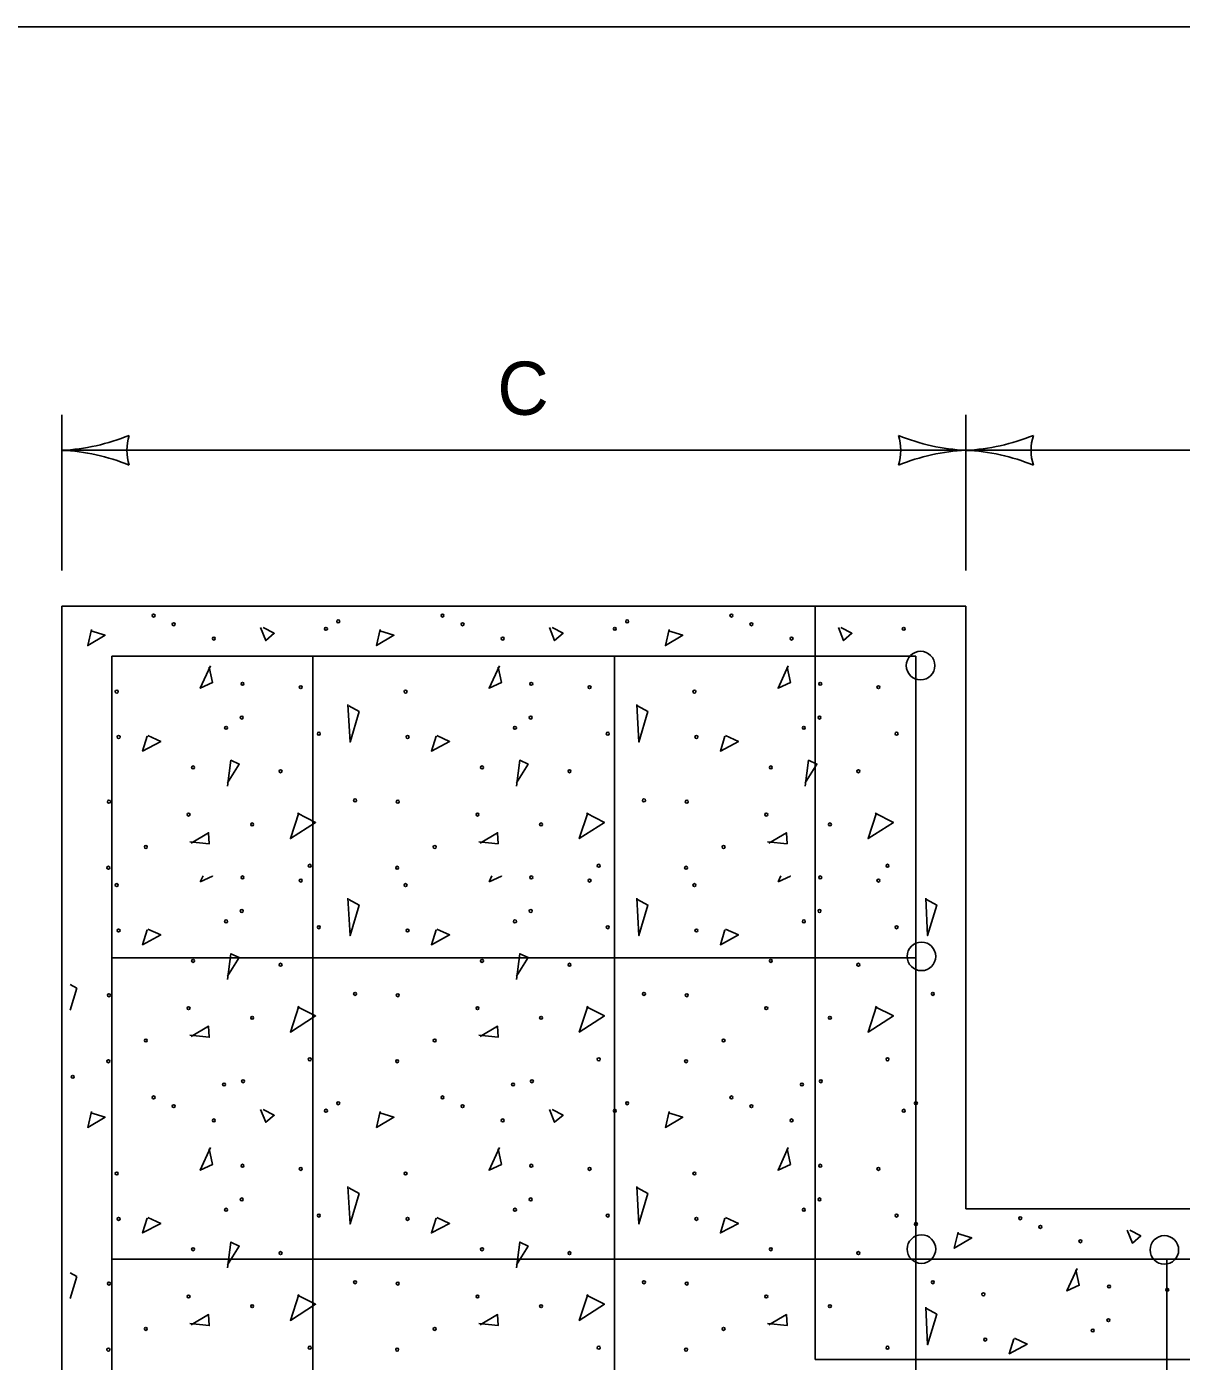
# Model space of a CAD drawing. Extents: x 49991.4 to 50021, y 49987.6 to 50011.4.
# Drawn here: x 50012.304 to 50013.607, y 49997.494 to 49998.999 of the extents above; entities that cross this region are included whole.
import ezdxf

# ---------------------------------------------------------------- set-up
doc = ezdxf.new("R2010")
doc.units = 0
for name, color, linetype in [('Level 1', 7, 'Continuous'), ('Level 2', 7, 'Continuous'), ('Level 3', 7, 'Continuous'), ('Level 4', 7, 'Continuous')]:
    doc.layers.add(name, color=color, linetype=linetype)

msp = doc.modelspace()

# ---------------------------------------------------------------- linework, layer by layer
at = {"layer": 'Level 1'}
for p, q in [((50012.3438, 49997.1556), (50012.3438, 49998.3456)), ((50012.3438, 49998.3456), (50013.3637, 49998.3456)), ((50013.3637, 49998.3456), (50013.3637, 49997.6657)), ((50012.4004, 49998.289), (50013.3071, 49998.289)), ((50012.4004, 49998.289), (50012.4004, 49997.2122)), ((50012.6271, 49998.289), (50012.6271, 49997.2122)), ((50012.9671, 49998.289), (50012.9671, 49997.2122)), ((50013.3071, 49998.289), (50013.3071, 49997.2122)), ((50012.4004, 49997.949), (50013.3071, 49997.949)), ((50013.3637, 49997.6657), (50014.0437, 49997.6657)), ((50012.4004, 49997.609), (50015.007, 49997.609)), ((50013.5904, 49997.609), (50013.5904, 49997.2122))]:
    msp.add_line(p, q, dxfattribs=at)
msp.add_lwpolyline([(49999.3835, 49998.9992), (50016.7501, 49998.9992), (50016.7501, 49987.7988), (49999.3835, 49987.7988)], close=True, dxfattribs=at)
for points in [[(50012.3773, 49998.3193), (50012.373, 49998.301), (50012.3926, 49998.3127), (50012.3766, 49998.3178)], [(50012.568, 49998.3214), (50012.5739, 49998.3068), (50012.5834, 49998.3149), (50012.571, 49998.3214)], [(50012.7031, 49998.3193), (50012.6988, 49998.301), (50012.7185, 49998.3127), (50012.7024, 49998.3178)], [(50012.894, 49998.3214), (50012.8997, 49998.3068), (50012.9093, 49998.3149), (50012.8968, 49998.3214)], [(50013.029, 49998.3193), (50013.0246, 49998.301), (50013.0443, 49998.3127), (50013.0282, 49998.3178)], [(50013.2198, 49998.3214), (50013.2256, 49998.3068), (50013.2351, 49998.3149), (50013.2227, 49998.3214)], [(50012.5117, 49998.2784), (50012.5, 49998.2529), (50012.5138, 49998.2594), (50012.5102, 49998.2769)], [(50012.8375, 49998.2784), (50012.8258, 49998.2529), (50012.8397, 49998.2594), (50012.836, 49998.2769)], [(50013.1633, 49998.2784), (50013.1517, 49998.2529), (50013.1656, 49998.2594), (50013.1619, 49998.2769)], [(50012.6666, 49998.2345), (50012.6689, 49998.1922), (50012.6791, 49998.2266), (50012.6674, 49998.2331)], [(50012.9924, 49998.2345), (50012.9947, 49998.1922), (50013.0049, 49998.2266), (50012.9932, 49998.2331)], [(50012.4401, 49998.1988), (50012.435, 49998.182), (50012.4555, 49998.1929), (50012.4409, 49998.1995)], [(50012.766, 49998.1988), (50012.7608, 49998.182), (50012.7813, 49998.1929), (50012.7667, 49998.1995)], [(50013.0918, 49998.1988), (50013.0867, 49998.182), (50013.1071, 49998.1929), (50013.0925, 49998.1995)], [(50012.5308, 49998.1426), (50012.5345, 49998.1717), (50012.544, 49998.1674), (50012.5308, 49998.1462)], [(50012.8567, 49998.1426), (50012.8603, 49998.1717), (50012.8698, 49998.1674), (50012.8567, 49998.1462)], [(50013.1825, 49998.1426), (50013.1861, 49998.1717), (50013.1956, 49998.1674), (50013.1825, 49998.1462)], [(50012.6112, 49998.1126), (50012.6017, 49998.0834), (50012.6301, 49998.1017), (50012.6097, 49998.1119)], [(50012.937, 49998.1126), (50012.9275, 49998.0834), (50012.9559, 49998.1017), (50012.9355, 49998.1119)], [(50013.2628, 49998.1126), (50013.2533, 49998.0834), (50013.2819, 49998.1017), (50013.2614, 49998.1119)], [(50012.4897, 49998.0783), (50012.5094, 49998.09), (50012.5102, 49998.0775), (50012.4883, 49998.0797)], [(50012.8156, 49998.0783), (50012.8354, 49998.09), (50012.836, 49998.0775), (50012.8142, 49998.0797)], [(50013.1415, 49998.0783), (50013.1612, 49998.09), (50013.1619, 49998.0775), (50013.14, 49998.0797)], [(50012.5031, 49998.0413), (50012.5, 49998.0346)], [(50012.5, 49998.0346), (50012.5138, 49998.0411)], [(50012.5138, 49998.0411), (50012.5138, 49998.0413)], [(50012.8289, 49998.0413), (50012.8258, 49998.0346)], [(50012.8258, 49998.0346), (50012.8397, 49998.0411)], [(50012.8397, 49998.0411), (50012.8397, 49998.0413)], [(50013.1547, 49998.0413), (50013.1517, 49998.0346)], [(50013.1517, 49998.0346), (50013.1656, 49998.0411)], [(50013.1656, 49998.0411), (50013.1655, 49998.0413)], [(50012.6666, 49998.0163), (50012.6689, 49997.9739), (50012.6791, 49998.0083), (50012.6674, 49998.0148)], [(50012.9924, 49998.0163), (50012.9947, 49997.9739), (50013.0049, 49998.0083), (50012.9932, 49998.0148)], [(50013.3184, 49998.0163), (50013.3205, 49997.9739), (50013.3307, 49998.0083), (50013.3191, 49998.0148)], [(50012.4401, 49997.9805), (50012.435, 49997.9637), (50012.4555, 49997.9747), (50012.4409, 49997.9813)], [(50012.766, 49997.9805), (50012.7608, 49997.9637), (50012.7813, 49997.9747), (50012.7667, 49997.9813)], [(50013.0918, 49997.9805), (50013.0867, 49997.9637), (50013.1071, 49997.9747), (50013.0925, 49997.9813)], [(50012.5308, 49997.9243), (50012.5345, 49997.9535), (50012.544, 49997.9491), (50012.5308, 49997.928)], [(50012.8567, 49997.9243), (50012.8603, 49997.9535), (50012.8698, 49997.9491), (50012.8567, 49997.928)], [(50012.3606, 49997.9147), (50012.3531, 49997.9189)], [(50012.3531, 49997.8897), (50012.3606, 49997.9147)], [(50012.6112, 49997.8944), (50012.6017, 49997.8651), (50012.6301, 49997.8834), (50012.6097, 49997.8937)], [(50012.937, 49997.8944), (50012.9275, 49997.8651), (50012.9559, 49997.8834), (50012.9355, 49997.8937)], [(50013.2628, 49997.8944), (50013.2533, 49997.8651), (50013.2819, 49997.8834), (50013.2614, 49997.8937)], [(50012.4897, 49997.86), (50012.5094, 49997.8717), (50012.5102, 49997.8593), (50012.4883, 49997.8615)], [(50012.8156, 49997.86), (50012.8354, 49997.8717), (50012.836, 49997.8593), (50012.8142, 49997.8615)], [(50012.568, 49997.7779), (50012.5739, 49997.7634), (50012.5834, 49997.7713), (50012.571, 49997.7779)], [(50012.894, 49997.7779), (50012.8997, 49997.7634), (50012.9093, 49997.7713), (50012.8968, 49997.7779)], [(50012.3773, 49997.7757), (50012.373, 49997.7575), (50012.3926, 49997.7691), (50012.3766, 49997.7742)], [(50012.7031, 49997.7757), (50012.6988, 49997.7575), (50012.7185, 49997.7691), (50012.7024, 49997.7742)], [(50013.029, 49997.7757), (50013.0246, 49997.7575), (50013.0443, 49997.7691), (50013.0282, 49997.7742)], [(50012.5117, 49997.7348), (50012.5, 49997.7093), (50012.5138, 49997.7159), (50012.5102, 49997.7333)], [(50012.8375, 49997.7348), (50012.8258, 49997.7093), (50012.8397, 49997.7159), (50012.836, 49997.7333)], [(50013.1633, 49997.7348), (50013.1517, 49997.7093), (50013.1656, 49997.7159), (50013.1619, 49997.7333)], [(50012.6666, 49997.691), (50012.6689, 49997.6487), (50012.6791, 49997.683), (50012.6674, 49997.6896)], [(50012.9924, 49997.691), (50012.9947, 49997.6487), (50013.0049, 49997.683), (50012.9932, 49997.6896)], [(50012.4401, 49997.6552), (50012.435, 49997.6385), (50012.4555, 49997.6493), (50012.4409, 49997.6559)], [(50012.766, 49997.6552), (50012.7608, 49997.6385), (50012.7813, 49997.6493), (50012.7667, 49997.6559)], [(50013.0918, 49997.6552), (50013.0867, 49997.6385), (50013.1071, 49997.6493), (50013.0925, 49997.6559)], [(50012.5308, 49997.599), (50012.5345, 49997.6283), (50012.544, 49997.6238), (50012.5308, 49997.6026)], [(50012.8567, 49997.599), (50012.8603, 49997.6283), (50012.8698, 49997.6238), (50012.8567, 49997.6026)], [(50013.3549, 49997.6395), (50013.3504, 49997.6212), (50013.3702, 49997.6329), (50013.3541, 49997.638)], [(50013.5456, 49997.6416), (50013.5515, 49997.627), (50013.5609, 49997.6351), (50013.5485, 49997.6416)], [(50013.4893, 49997.5986), (50013.4775, 49997.5731), (50013.4914, 49997.5796), (50013.4878, 49997.5971)], [(50012.3606, 49997.5893), (50012.3531, 49997.5935)], [(50012.3531, 49997.5644), (50012.3606, 49997.5893)], [(50012.6112, 49997.5691), (50012.6017, 49997.5399), (50012.6301, 49997.5581), (50012.6097, 49997.5683)], [(50012.937, 49997.5691), (50012.9275, 49997.5399), (50012.9559, 49997.5581), (50012.9355, 49997.5683)], [(50013.3184, 49997.5547), (50013.3205, 49997.5124), (50013.3307, 49997.5468), (50013.3191, 49997.5533)], [(50012.4897, 49997.5348), (50012.5094, 49997.5464), (50012.5102, 49997.534), (50012.4883, 49997.5362)], [(50012.8156, 49997.5348), (50012.8354, 49997.5464), (50012.836, 49997.534), (50012.8142, 49997.5362)], [(50013.1415, 49997.5348), (50013.1612, 49997.5464), (50013.1619, 49997.534), (50013.14, 49997.5362)], [(50013.4176, 49997.519), (50013.4125, 49997.5022), (50013.4329, 49997.5131), (50013.4184, 49997.5197)]]:
    msp.add_lwpolyline(points, dxfattribs=at)
for centre, radius in [((50012.4474, 49998.3349), 0.00165), ((50012.7732, 49998.3349), 0.00165), ((50013.0991, 49998.3349), 0.00165), ((50012.47, 49998.3251), 0.00165), ((50012.6418, 49998.32), 0.00165), ((50012.6556, 49998.3284), 0.00165), ((50012.7959, 49998.3251), 0.00165), ((50012.9676, 49998.32), 0.00165), ((50012.9815, 49998.3284), 0.00165), ((50013.1217, 49998.3251), 0.00165), ((50013.2935, 49998.32), 0.00165), ((50012.5153, 49998.309), 0.00165), ((50012.8411, 49998.309), 0.00165), ((50013.167, 49998.309), 0.00165), ((50013.3125, 49998.2785), 0.0161), ((50012.5476, 49998.2579), 0.00165), ((50012.8734, 49998.2579), 0.00165), ((50013.1993, 49998.2579), 0.00165), ((50012.4057, 49998.2491), 0.00165), ((50012.6133, 49998.2542), 0.00165), ((50012.7316, 49998.2491), 0.00165), ((50012.9391, 49998.2542), 0.00165), ((50013.0574, 49998.2491), 0.00165), ((50013.265, 49998.2542), 0.00165), ((50012.5468, 49998.2199), 0.00165), ((50012.8727, 49998.2199), 0.00165), ((50013.1985, 49998.2199), 0.00165), ((50012.4079, 49998.198), 0.00165), ((50012.5291, 49998.2083), 0.00165), ((50012.6337, 49998.2017), 0.00165), ((50012.7338, 49998.198), 0.00165), ((50012.855, 49998.2083), 0.00165), ((50012.9596, 49998.2017), 0.00165), ((50013.0596, 49998.198), 0.00165), ((50013.1808, 49998.2083), 0.00165), ((50013.2854, 49998.2017), 0.00165), ((50012.4919, 49998.1637), 0.00165), ((50012.5906, 49998.1593), 0.00165), ((50012.8178, 49998.1637), 0.00165), ((50012.9165, 49998.1593), 0.00165), ((50013.1436, 49998.1637), 0.00165), ((50013.2423, 49998.1593), 0.00165), ((50012.397, 49998.125), 0.00165), ((50012.6746, 49998.1265), 0.00165), ((50012.7228, 49998.125), 0.00165), ((50013.0005, 49998.1265), 0.00165), ((50013.0487, 49998.125), 0.00165), ((50012.4868, 49998.1104), 0.00165), ((50012.8127, 49998.1104), 0.00165), ((50013.1385, 49998.1104), 0.00165), ((50012.5585, 49998.0994), 0.00165), ((50012.8844, 49998.0994), 0.00165), ((50013.2102, 49998.0994), 0.00165), ((50012.4386, 49998.0739), 0.00165), ((50012.7644, 49998.0739), 0.00165), ((50013.0903, 49998.0739), 0.00165), ((50012.3963, 49998.0505), 0.00165), ((50012.6235, 49998.0527), 0.00165), ((50012.7221, 49998.0505), 0.00165), ((50012.9494, 49998.0527), 0.00165), ((50013.048, 49998.0505), 0.00165), ((50013.2752, 49998.0527), 0.00165), ((50012.5476, 49998.0396), 0.00165), ((50012.6133, 49998.036), 0.00165), ((50012.8734, 49998.0396), 0.00165), ((50012.9391, 49998.036), 0.00165), ((50013.1993, 49998.0396), 0.00165), ((50013.265, 49998.036), 0.00165), ((50012.4057, 49998.0309), 0.00165), ((50012.7316, 49998.0309), 0.00165), ((50013.0574, 49998.0309), 0.00165), ((50012.5468, 49998.0017), 0.00165), ((50012.8727, 49998.0017), 0.00165), ((50013.1985, 49998.0017), 0.00165), ((50012.5291, 49997.99), 0.00165), ((50012.855, 49997.99), 0.00165), ((50013.1808, 49997.99), 0.00165), ((50012.4079, 49997.9797), 0.00165), ((50012.6337, 49997.9834), 0.00165), ((50012.7338, 49997.9797), 0.00165), ((50012.9596, 49997.9834), 0.00165), ((50013.0596, 49997.9797), 0.00165), ((50013.2854, 49997.9834), 0.00165), ((50013.3135, 49997.9505), 0.0161), ((50012.4919, 49997.9454), 0.00165), ((50012.8178, 49997.9454), 0.00165), ((50013.1436, 49997.9454), 0.00165), ((50012.5906, 49997.9411), 0.00165), ((50012.9165, 49997.9411), 0.00165), ((50013.2423, 49997.9411), 0.00165), ((50012.397, 49997.9067), 0.00165), ((50012.6746, 49997.9082), 0.00165), ((50012.7228, 49997.9067), 0.00165), ((50013.0005, 49997.9082), 0.00165), ((50013.0487, 49997.9067), 0.00165), ((50013.3263, 49997.9082), 0.00165), ((50012.4868, 49997.8921), 0.00165), ((50012.5585, 49997.8812), 0.00165), ((50012.8127, 49997.8921), 0.00165), ((50012.8844, 49997.8812), 0.00165), ((50013.1385, 49997.8921), 0.00165), ((50013.2102, 49997.8812), 0.00165), ((50012.4386, 49997.8556), 0.00165), ((50012.7644, 49997.8556), 0.00165), ((50013.0903, 49997.8556), 0.00165), ((50012.3963, 49997.8322), 0.00165), ((50012.6235, 49997.8344), 0.00165), ((50012.7221, 49997.8322), 0.00165), ((50012.9494, 49997.8344), 0.00165), ((50013.048, 49997.8322), 0.00165), ((50013.2752, 49997.8344), 0.00165), ((50012.3561, 49997.8146), 0.00165), ((50012.5269, 49997.806), 0.00165), ((50012.5483, 49997.8096), 0.00165), ((50012.8528, 49997.806), 0.00165), ((50012.8741, 49997.8096), 0.00165), ((50013.1787, 49997.806), 0.00165), ((50013.2, 49997.8096), 0.00165), ((50012.4474, 49997.7914), 0.00165), ((50012.7732, 49997.7914), 0.00165), ((50013.0991, 49997.7914), 0.00165), ((50012.47, 49997.7815), 0.00165), ((50012.6418, 49997.7764), 0.00165), ((50012.6556, 49997.7848), 0.00165), ((50012.7959, 49997.7815), 0.00165), ((50012.9676, 49997.7764), 0.00165), ((50012.9815, 49997.7848), 0.00165), ((50013.1217, 49997.7815), 0.00165), ((50013.2935, 49997.7764), 0.00165), ((50013.3073, 49997.7848), 0.00165), ((50012.5153, 49997.7655), 0.00165), ((50012.8411, 49997.7655), 0.00165), ((50013.167, 49997.7655), 0.00165), ((50012.4057, 49997.7056), 0.00165), ((50012.5476, 49997.7143), 0.00165), ((50012.6133, 49997.7107), 0.00165), ((50012.7316, 49997.7056), 0.00165), ((50012.8734, 49997.7143), 0.00165), ((50012.9391, 49997.7107), 0.00165), ((50013.0574, 49997.7056), 0.00165), ((50013.1993, 49997.7143), 0.00165), ((50013.265, 49997.7107), 0.00165), ((50012.5468, 49997.6764), 0.00165), ((50012.8727, 49997.6764), 0.00165), ((50013.1985, 49997.6764), 0.00165), ((50012.5291, 49997.6647), 0.00165), ((50012.6337, 49997.6581), 0.00165), ((50012.855, 49997.6647), 0.00165), ((50012.9596, 49997.6581), 0.00165), ((50013.1808, 49997.6647), 0.00165), ((50013.2854, 49997.6581), 0.00165), ((50012.4079, 49997.6544), 0.00165), ((50012.7338, 49997.6544), 0.00165), ((50013.0596, 49997.6544), 0.00165), ((50013.3073, 49997.6486), 0.00165), ((50013.4249, 49997.6551), 0.00165), ((50013.4476, 49997.6453), 0.00165), ((50013.3135, 49997.6203), 0.0161), ((50013.4928, 49997.6292), 0.00165), ((50013.5875, 49997.6194), 0.0161), ((50012.4919, 49997.6201), 0.00165), ((50012.5906, 49997.6158), 0.00165), ((50012.8178, 49997.6201), 0.00165), ((50012.9165, 49997.6158), 0.00165), ((50013.1436, 49997.6201), 0.00165), ((50013.2423, 49997.6158), 0.00165), ((50012.397, 49997.5814), 0.00165), ((50012.6746, 49997.5829), 0.00165), ((50012.7228, 49997.5814), 0.00165), ((50013.0005, 49997.5829), 0.00165), ((50013.0487, 49997.5814), 0.00165), ((50013.3263, 49997.5829), 0.00165), ((50012.4868, 49997.5668), 0.00165), ((50012.8127, 49997.5668), 0.00165), ((50013.1385, 49997.5668), 0.00165), ((50013.3833, 49997.5693), 0.00165), ((50013.5251, 49997.5781), 0.00165), ((50013.5908, 49997.5744), 0.00165), ((50012.5585, 49997.5559), 0.00165), ((50012.8844, 49997.5559), 0.00165), ((50013.2102, 49997.5559), 0.00165), ((50013.5244, 49997.5401), 0.00165), ((50012.4386, 49997.5303), 0.00165), ((50012.7644, 49997.5303), 0.00165), ((50013.0903, 49997.5303), 0.00165), ((50013.5067, 49997.5285), 0.00165), ((50012.3963, 49997.5069), 0.00165), ((50012.6235, 49997.5091), 0.00165), ((50012.7221, 49997.5069), 0.00165), ((50012.9494, 49997.5091), 0.00165), ((50013.048, 49997.5069), 0.00165), ((50013.2752, 49997.5091), 0.00165), ((50013.3855, 49997.5182), 0.00165)]:
    msp.add_circle(centre, radius, dxfattribs=at)
at = {"layer": 'Level 3'}
for p, q in [((50012.3438, 49998.3856), (50012.3438, 49998.5614)), ((50013.3637, 49998.3856), (50013.3637, 49998.5614)), ((50012.3438, 49998.5214), (50015.0637, 49998.5214))]:
    msp.add_line(p, q, dxfattribs=at)
for centre, radius, start, end in [((50012.3323, 49998.7541), 0.233, 272.8273, 292.0772), ((50012.472, 49998.5214), 0.0548, 162.1388, 197.8612), ((50013.3728, 49998.7435), 0.2223, 247.456, 267.6395), ((50013.2354, 49998.5214), 0.0548, 342.1388, 17.8612), ((50013.3522, 49998.7541), 0.233, 272.8273, 292.0772), ((50013.4919, 49998.5214), 0.0548, 162.1388, 197.8612), ((50012.3346, 49998.2992), 0.2223, 67.456, 87.6395), ((50013.3752, 49998.2887), 0.233, 92.8273, 112.0772), ((50013.3545, 49998.2992), 0.2223, 67.456, 87.6395)]:
    msp.add_arc(centre, radius, start, end, dxfattribs=at)
at = {"layer": 'Level 4'}
for p, q in [((50013.1937, 49998.3456), (50013.1937, 49997.4956)), ((50013.1937, 49997.4956), (50014.2137, 49997.4956))]:
    msp.add_line(p, q, dxfattribs=at)

# ---------------------------------------------------------------- texts
at = {"layer": 'Level 2'}
msp.add_text('C', height=0.06, dxfattribs=at).set_placement((50012.8351, 49998.5614))

doc.saveas('drawing.dxf')
